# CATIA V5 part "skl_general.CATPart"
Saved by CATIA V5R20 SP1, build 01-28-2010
Part number: skl_general
Publications: "A", "C", "E", "O", "B", "G", "D", "Plan.1", "OB"
Bounding box of the stored display mesh (mm): x 0 to 0, y -983.26 to 0, z -200 to 338.703
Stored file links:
  C:\Users\patrice\Desktop\IFMa\Semestre 3\IAO\projet iao\iao\skl_general.CATPart
  C:\Users\patrice\Desktop\IFMa\Semestre 3\IAO\projet iao\iao\skl_iao_755.CATProduct
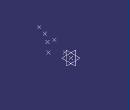
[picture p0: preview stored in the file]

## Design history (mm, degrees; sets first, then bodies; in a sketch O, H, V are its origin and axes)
External parameters (linked from other documents)
  External.AC = 200 mm
Set1
  Point1 "A": (0, 0, 0)
  Circle1 "AC": type CtrRad, Start 0, End 180, Center Point1, Support Plane1, Radius 200 {= External.AC}, FirstDirection (0, 1, 0)
  Point2 "C": type OnCurve, Support Circle1, RefPoint Point3, Ratio 0.7, Direction (0, 0, 1)
  Circle2 "AE": type CtrRad, Start 0, End 180, Center Point1, Support Plane1, Radius 728 {= 3.64*External.AC}, FirstDirection (0, 1, 0)
  Point3 "référence_pour_E": (0, 0, -200 {= -External.AC})
  Point4 "E": type OnCurve, Support Circle2, RefPoint Point3, Offset 0, Direction xy-plane
  Extract1 "E": ExtractElem vertex of Point4
  Circle3 "AO": type CtrRad, Start 0, End 180, Center Point1, Support Plane1, Radius 564 {= 2.82*External.AC}, FirstDirection (0, 1, 0)
  Circle4 "OE": type CtrRad, Start 0, End 180, Center Extract1, Support Plane1, Radius 476 {= 2.38*External.AC}, FirstDirection (0, 1, 0)
  Intersect1: ToIntersect1 Circle3, ToIntersect2 Circle4
  Extract2 "O": ExtractElem vertex of Intersect1
  Circle5 "OB": type CtrRad, Start 0, End 180, Center Extract2, Support Plane1, Radius 272 {= 1.36*External.AC}, FirstDirection (0, 1, 0)
  Circle6 "CB": type CtrRad, Start 0, End 180, Center Point2, Support Plane1, Radius 536 {= 2.68*External.AC}, FirstDirection (0, 1, 0)
  Intersect2: ToIntersect1 Circle6, ToIntersect2 Circle5
  Extract3 "B": ExtractElem vertex of Intersect2
  Circle7 "BG": type CtrRad, Start 0, End 180, Center Extract3, Support Plane1, Radius 372 {= 1.86*External.AC}, FirstDirection (0, 1, 0)
  Circle8 "CG": type CtrRad, Start 0, End 180, Center Point2, Support Plane1, Radius 840 {= 4.2*External.AC}, FirstDirection (0, 1, 0)
  Intersect3: ToIntersect1 Circle8, ToIntersect2 Circle7
  Extract4 "G": ExtractElem vertex of Intersect3
  Circle9 "DG": type CtrRad, Start 0, End 180, Center Extract4, Support Plane1, Radius 200 {= External.AC}, FirstDirection (0, 1, 0)
  Circle10 "ED": type CtrRad, Start 0, End 180, Center Extract1, Support Plane1, Radius 464 {= 2.32*External.AC}, FirstDirection (0, 1, 0)
  Intersect4: ToIntersect1 Circle10, ToIntersect2 Circle9
  Extract5 "D": ExtractElem vertex of Intersect4
  Plane1: type Offset, RefPlane yz-plane, Offset 0
Body1 (main body)
Relations
  Point3.Z = -AC (deactivated)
